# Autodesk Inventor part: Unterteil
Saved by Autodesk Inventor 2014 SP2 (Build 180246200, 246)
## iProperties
Created: 2015-06
Part Number: Unterteil
Material: Generisch
Document SubType Name: Modeling
Designer: e_krauts
Density: 1 g/cm^3
Appearance: Vorgabe
Mass: 3067.85 g
Surface Area: 3305.84 cm^2
Volume: 3067.85 cm^3
Sending System: SolidWorks 2011
Last Author: e_boekem
Author: e_krauts
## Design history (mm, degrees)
node "Unterteil.ipt1"
node "Aufsatz-Linear austragen3"
node "Basis1"
